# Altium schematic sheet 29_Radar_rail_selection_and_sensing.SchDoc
size 289 x 396 mm
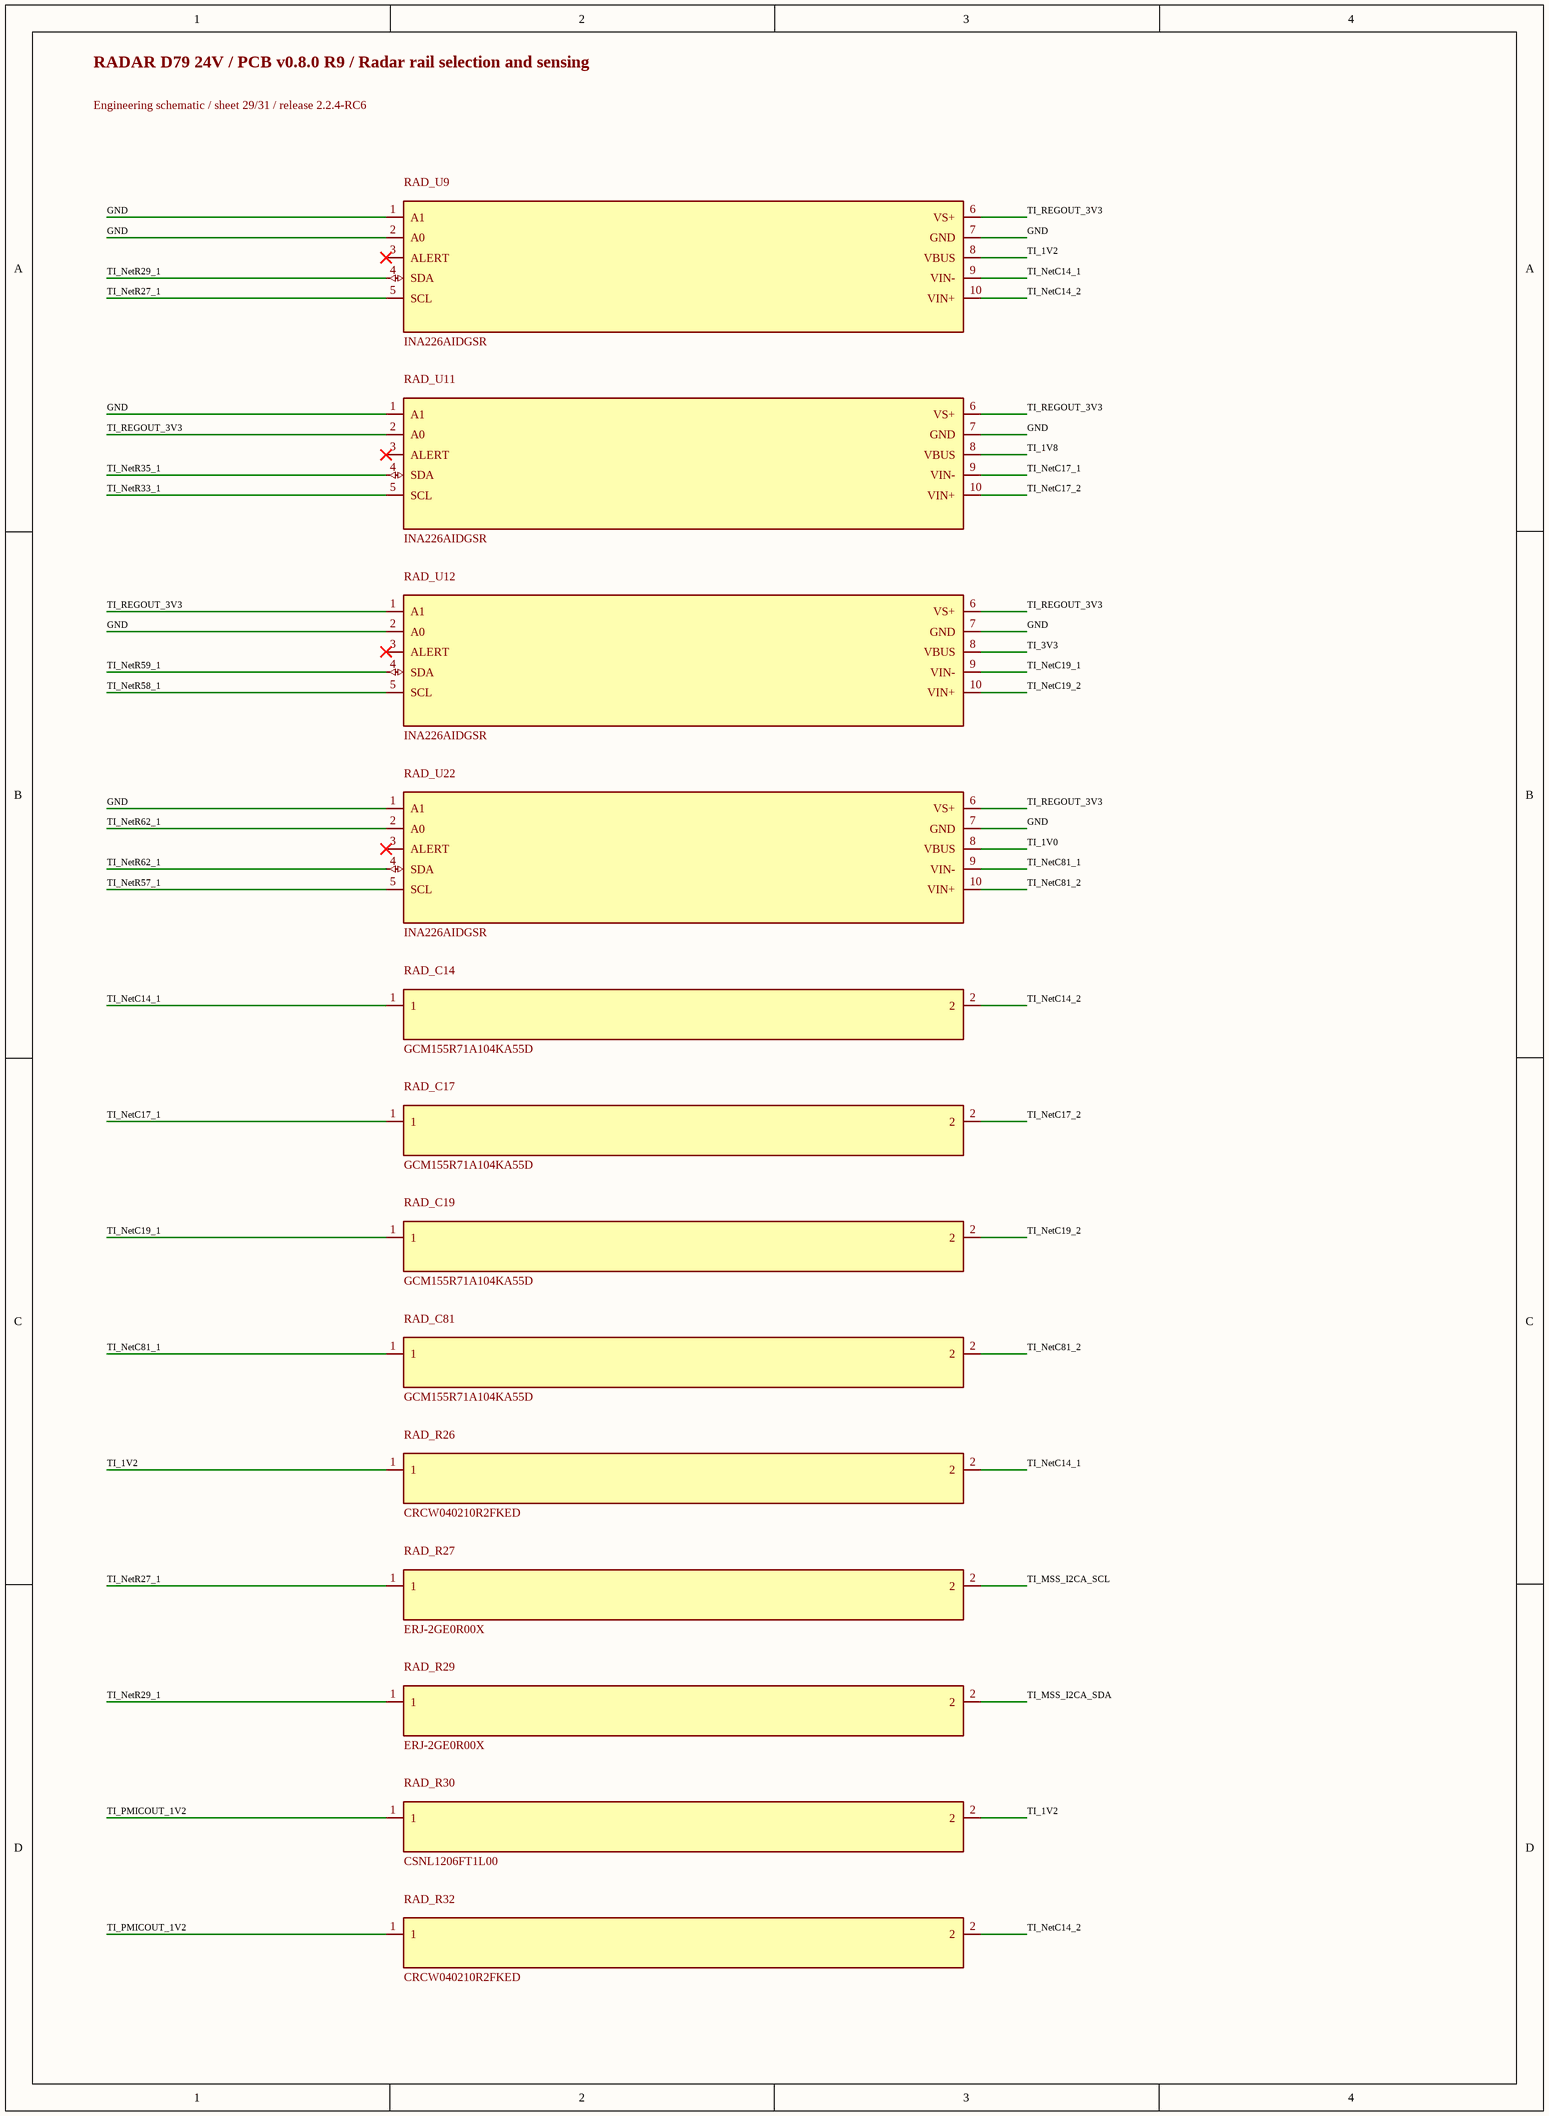
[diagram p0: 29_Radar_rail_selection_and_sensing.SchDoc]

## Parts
RAD_C14  GCM155R71A104KA55D  [0402L]
RAD_C17  GCM155R71A104KA55D  [0402L]
RAD_C19  GCM155R71A104KA55D  [0402L]
RAD_C81  GCM155R71A104KA55D  [0402L]
RAD_R26  CRCW040210R2FKED  [0402L]
RAD_R27  ERJ-2GE0R00X  [0402L]
RAD_R29  ERJ-2GE0R00X  [0402L]
RAD_R30  CSNL1206FT1L00  [1206L]
RAD_R32  CRCW040210R2FKED  [0402L]
RAD_U9  INA226AIDGSR  [DGS0010A_L]
RAD_U11  INA226AIDGSR  [DGS0010A_L]
RAD_U12  INA226AIDGSR  [DGS0010A_L]
RAD_U22  INA226AIDGSR  [DGS0010A_L]

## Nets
GND: RAD_U9.1(A1) RAD_U9.2(A0) RAD_U9.7(GND) RAD_U11.1(A1) RAD_U11.7(GND) RAD_U12.2(A0) RAD_U12.7(GND) RAD_U22.1(A1) RAD_U22.7(GND)
TI_1V0: RAD_U22.8(VBUS)
TI_1V2: RAD_R26.1 RAD_R30.2 RAD_U9.8(VBUS)
TI_1V8: RAD_U11.8(VBUS)
TI_3V3: RAD_U12.8(VBUS)
TI_MSS_I2CA_SCL: RAD_R27.2
TI_MSS_I2CA_SDA: RAD_R29.2
TI_NetC14_1: RAD_C14.1 RAD_R26.2 RAD_U9.9(VIN-)
TI_NetC14_2: RAD_C14.2 RAD_R32.2 RAD_U9.10(VIN+)
TI_NetC17_1: RAD_C17.1 RAD_U11.9(VIN-)
TI_NetC17_2: RAD_C17.2 RAD_U11.10(VIN+)
TI_NetC19_1: RAD_C19.1 RAD_U12.9(VIN-)
TI_NetC19_2: RAD_C19.2 RAD_U12.10(VIN+)
TI_NetC81_1: RAD_C81.1 RAD_U22.9(VIN-)
TI_NetC81_2: RAD_C81.2 RAD_U22.10(VIN+)
TI_NetR27_1: RAD_R27.1 RAD_U9.5(SCL)
TI_NetR29_1: RAD_R29.1 RAD_U9.4(SDA)
TI_NetR33_1: RAD_U11.5(SCL)
TI_NetR35_1: RAD_U11.4(SDA)
TI_NetR57_1: RAD_U22.5(SCL)
TI_NetR58_1: RAD_U12.5(SCL)
TI_NetR59_1: RAD_U12.4(SDA)
TI_NetR62_1: RAD_U22.2(A0) RAD_U22.4(SDA)
TI_PMICOUT_1V2: RAD_R30.1 RAD_R32.1
TI_REGOUT_3V3: RAD_U9.6(VS+) RAD_U11.2(A0) RAD_U11.6(VS+) RAD_U12.1(A1) RAD_U12.6(VS+) RAD_U22.6(VS+)

Not connected (* = marked no-connect by the designer): RAD_U9 3(ALERT)*; RAD_U11 3(ALERT)*; RAD_U12 3(ALERT)*; RAD_U22 3(ALERT)*

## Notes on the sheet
- RADAR D79 24V / PCB v0.8.0 R9 / Radar rail selection and sensing
- Engineering schematic / sheet 29/31 / release 2.2.4-RC6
